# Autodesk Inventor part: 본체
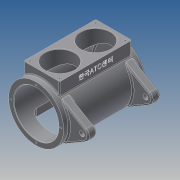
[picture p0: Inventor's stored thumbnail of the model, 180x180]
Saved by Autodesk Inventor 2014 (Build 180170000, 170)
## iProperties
Created: 2016-11
Part Number: 본체
Material: 알루미늄 6061
Document SubType Name: Modeling
Designer: mduedu
Density: 2.71 g/cm^3
Appearance: 기본값
Mass: 2578.28 g
Surface Area: 1746.6 cm^2
Volume: 951.394 cm^3
Author: mduedu
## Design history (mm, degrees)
sketch "스케치1"
  geometry: C1 r 65 at (0, 0); 1 further point
  constraints: 1 centre point, 1 coincident
  dimensions: "d119" = 130 diameter of C1
extrude "돌출1" new body sketch "스케치1" distance "d3" = 98; taper "d4" = 0 deg; dims "d132" = 97, "d133" = 0
feature "쉘1" dims "d120" = 12, "d134" = 8
node "작업 평면2"
sketch "스케치13"
  geometry: L1 (42.5, 85)-(-42.5, 85); L2 (-42.5, 85)-(-42.5, -85); L3 (-42.5, -85)-(42.5, -85); L4 (42.5, -85)-(42.5, 85); 2 further points
  constraints: 8 end point, 2 parallel, 1 horizontal, 1 midpoint, 1 perpendicular, 1 vertical alignment
  dimensions: "d122" = 170 distance of L1.end L2.end; "d124" = 85 distance of L2.end L3.end; "d125" = 85 distance from line of point (0, 0) L1 (= 0.5 x d122)
extrude "돌출11" join sketch "스케치13" stored distance "d126" = 10; taper "d127" = 0 deg
sketch "스케치14"
  geometry: L1 (65, 97)-(-65, 97) reference; C1 r 35 at (0, 42.5); 1 further point
  constraints: 1 centre point, 1 vertical alignment
  dimensions: "d128" = 70 diameter of C1; "d129" = 54.5 distance from line of C1.centre L1
extrude "돌출12" cut sketch "스케치14" stored distance "d130" = 10; taper "d131" = 0 deg
sketch "스케치15"
  geometry: C1 r 53 at (0, 0) reference; 1 further point
extrude "돌출13" cut sketch "스케치15" stored distance "d135" = 10; taper "d136" = 0 deg
chamfer "모따기1" distance "d54" = 1; stored, may be unused: second distance "d55" = 2, angle "d56" = 45 deg
sketch "스케치8"
  geometry: C1 r 23 at (0, 0); C2 r 65 at (0, 0) reference; 1 further point
  constraints: 1 centre point, 1 concentric
  dimensions: "d57" = 46 diameter of C1
extrude "돌출8" join sketch "스케치8" distance "d58" = 14; taper "d59" = 0 deg
feature "면 기울기1" dims angle "d202" = 10 deg
hole "구멍3" diameter "d62" = 24; stored, may be unused: countersink angle "d66" = 90 deg, drill point angle "d68" = 0 deg; dims "d63" = 6, "d64" = 28, "d65" = 8, "d67" = 14, "d169" = 10, "d170" = 10
fillet "모깎기11" dims "d69" = 3
fillet "모깎기12" dims "d70" = 3
fillet "모깎기13" dims "d71" = 0.3
chamfer "모따기2" distance "d72" = 1; stored, may be unused: second distance "d73" = 2, angle "d74" = 45 deg
node "작업 평면3"
sketch "스케치16"
  geometry: L1 (-42.5, -80)-(52.5, -80); L2 (-42.5, -80)-(24.675, -12.825); L3 (-42.5, -80)-(24.675, -147.175); L4 (3.462, -34.038)-(60.057, -67.042); L5 (3.462, -125.962)-(60.057, -92.958); A1 r 65 centre (-42.5, -80) between (3.462, -34.038) and (3.462, -125.962) reference; A2 r 65 centre (-42.5, -80) between (3.462, -125.962) and (3.462, -34.038); A3 r 95 centre (-42.5, -80) between (52.5, -80) and (24.675, -147.175); A4 r 15 centre (52.5, -80) between (60.057, -67.042) and (60.057, -92.958); 1 further point
  constraints: 10 end point, 9 point on circle, 3 centre point, 3 coincident, 2 point on line, 2 tangent, 1 horizontal
  dimensions: "d140" = 45 deg angle of L3 L1; "d141" = 45 deg angle of L2 L1; "d194" = 30 radial gap between concentric circles of A3 A1; "d195" = 30 diameter of A4
extrude "돌출14" join sketch "스케치16" distance "d143" = 20; taper "d144" = 0 deg
fillet "모깎기25" dims "d196" = 3
fillet "모깎기26" dims "d197" = 3
sketch "스케치22"
  geometry: C1 r 6 at (52.5, -80); A1 r 15 centre (52.5, -80) between (60.057, -92.958) and (60.057, -67.042) reference; 1 further point
  constraints: 1 centre point, 1 coincident
  dimensions: "d198" = 12 diameter of C1
extrude "돌출17" cut sketch "스케치22" stored distance "d200" = 10; taper "d201" = 0 deg
fillet "모깎기20" dims "d159" = 3
fillet "모깎기21" dims "d160" = 3
fillet "모깎기22" dims "d161" = 3
node "작업 평면4"
sketch "스케치18"
  geometry: L1 (-42.5, 65)-(42.5, 65); L2 (42.5, 65)-(42.5, -65); L3 (42.5, -65)-(-42.5, -65); L4 (-42.5, -65)-(-42.5, 65); 2 further points
  constraints: 8 end point, 2 parallel, 1 horizontal, 1 midpoint, 1 perpendicular, 1 vertical alignment
  dimensions: "d162" = 130 distance of L1.end L2.end; "d164" = 85 distance of L2.end L3.end; "d165" = 65 distance from line of point (0, 0) L1 (= 0.5 x d162)
extrude "돌출16" cut sketch "스케치18" stored distance "d166" = 15; taper "d167" = 0 deg
fillet "모깎기23" dims "d168" = 10
fillet "모깎기24" dims "d173" = 3
sketch "스케치19"
  geometry: 4 further points
  constraints: 4 other
hole "구멍6" sketch "스케치19" at (0, -59), (59, 0), (-59, 0), (0, 59) diameter "d174" = 3.242; stored, may be unused: countersink angle "d178" = 90 deg, drill point angle "d180" = 120 deg; dims "d175" = 7, "d176" = 4, "d177" = 2, "d179" = 9
sketch "스케치20"
  geometry: L1 (35, -77.5)-(-35, -77.5); L2 (-35, -77.5)-(-35, -7.5); L3 (-35, -7.5)-(35, -7.5); L4 (35, -7.5)-(35, -77.5); L5 (35, -77.5)-(-35, -7.5); L6 (-35, -77.5)-(35, -7.5); C1 r 36 at (0, -42.5) reference; 3 further points
  constraints: 12 end point, 2 coincident, 2 midpoint, 2 parallel, 1 horizontal, 1 perpendicular
  dimensions: "d181" = 70 distance of L2.end L3.end; "d182" = 70 distance of L1.end L2.end
hole "구멍7" sketch "스케치20" at (-35, -77.5), (35, -77.5) diameter "d183" = 3.242; stored, may be unused: countersink angle "d187" = 90 deg, drill point angle "d189" = 118 deg; dims "d184" = 7, "d185" = 4, "d186" = 2, "d188" = 9
sketch "스케치21"
  geometry: L1 (164, 0)-(0, 0) reference; L2 (-3, 0)-(-3, -24.649) reference; 3 further points
  constraints: 1 midpoint, 1 vertical alignment, 1 other
  dimensions: "d190" = 15 distance from line of point (82, -15) L1; "d191" = 85 distance from line of point (82, 0) L2 (derived)
feature "엠보싱2" sketch "스케치21" dims "d119" = 130, "d192" = 0.5, "d193" = 0
node "솔리드1"
mirror "대칭5"
mirror "대칭6"
mirror "대칭7"
